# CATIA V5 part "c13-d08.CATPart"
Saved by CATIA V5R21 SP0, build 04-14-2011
Part number: Part1
Material "Alpine Fir": density 500 kg/m3, Young's modulus 1.7e+10 Pa, Poisson ratio 0.45, thermal expansion 3.75e-06 1/K
Bounding box of the stored display mesh (mm): x -163 to 95, y -77.362 to 77.362, z -85 to 85
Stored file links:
  D:\CATIA V5R21 E-RESOURCES\CATIA-V5R21\catia-v5r21-Prts\c13_catia_v5r21_prt\c13_catia_v5r21_figr_13-29 & 30\c13-d08.CATPart
  C:\Program Files\Dassault Systemes\B21\win_b64\startup\materials\Catalog.CATMaterial
  C:\Program Files\Dassault Systemes\B21\win_b64\startup\materials\alpin_fir.jpg
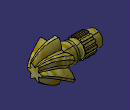
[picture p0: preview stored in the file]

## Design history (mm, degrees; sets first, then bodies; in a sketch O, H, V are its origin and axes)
Set1
  Plane1: type Offset, RefPlane face of Shaft1, Offset 45, reversed
  Plane2: type Offset, RefPlane Plane1, Offset 50, reversed
Body1 (main body), material "Alpine Fir"
  Sketch1 on zx-plane, origin (0, 0, 0), H (-1, 0, 0), V (0, 0, 1)
    axis line L1 (0, 0) -> (170, 0)
    line L2 (0, 0) -> (0, -45)
    point P2 (0, -45)
    line L3 (0, -45) -> (5, -45)
    point P3 (5, -45)
    line L4 (5, -45) -> (5, -39)
    line L5 (5, -39) -> (51, -39)
    line L6 (51, -39) -> (51, -38)
    point P6 (51, -38)
    line L7 (51, -38) -> (61, -38)
    point P7 (61, -38)
    line L8 (61, -38) -> (61, -36)
    point P8 (61, -36)
    arc A1 centre (72, -36) radius 11 from (61, -36) to (83, -36) cw
    point P10 (83, -36)
    line L9 (83, -36) -> (131, -36)
    line L10 (131, -36) -> (131, -32.5)
    line L11 (131, -32.5) -> (163, -32.5)
    line L12 (163, -32.5) -> (163, 0)
    point P14 (163, 0)
    line L13 (163, 0) -> (0, 0)
    "Radius" L11 L1 = 32.5
    "Radius" L9 L1 = 36
    "Radius" P7 L1 = 38
    "Radius" L5 L1 = 39
    "Radius" P3 L1 = 45
    length L11 = 32
    length L9 = 48
    distance P10 P8 = 22
    distance P7 P6 = 10
    length L5 = 46
    distance P3 P2 = 5
    horizontal: L1 H, L3 H, L5 H, L7 H, L9 H, L11 H, L13 H
    vertical: L2 V, L4 V, L6 V, L8 V, L12 V, L10 V
    tangency: A1 L8
    coincidence: P14 L1
  Shaft1: profile Sketch1, axis Sketch1.L1, angle 360
  Sketch2 on face of Shaft1, origin (-131, 0, 0), H (0, -1, 0), V (0, 0, 1)
    projected circle E1 centre (0, 0) radius 36 from edge [face of Shaft1 | face of Shaft1]
    projected arc E2 centre (0, 0) radius 36 from (5, 35.6511) to (-5, 35.6511) ccw from edge [face of Shaft1 | face of Shaft1]
    axis line L1 (0, 0) -> (0, 17.1744)
    point P2 (-5, 35.6511)
    line L2 (-5, 35.6511) -> (-5, 40.6511)
    point P3 (-5, 40.6511)
    line L3 (-5, 40.6511) -> (0, 40.6511)
    point P4 (0, 40.6511)
    point P5 (0, 40.6511)
    point P6 (5, 40.6511)
    line L4 (5, 40.6511) -> (0, 40.6511)
    point P7 (5, 35.6511)
    line L5 (5, 35.6511) -> (5, 40.6511)
    length L5 = 5
    distance L5 L2 = 10
    vertical: L1 V, L2 V
    coincidence: P2 E1, P4 L1, P4 P5
    horizontal: L3 H
    symmetry: P4 P5 L1, P3 P6 L1, L3 L4 L1, P2 P7 L1, L2 L5 L1
  Pad1: profile Sketch2, direction (1, 0, 0), length 48
  CircPattern1: of Pad1, instances 13, angular step 27.6923 {= 360.0*1 deg/CircPattern1.AngularNumber}, axis from face of Shaft1
  Loft1: solid, Sections (Sketch5; Sketch4; Sketch3)
  Sketch3 on Plane2, origin (95, 0, 0), H (0, -1, 0), V (0, 0, 1)
    construction line L1 through (0, 0) direction (1, 0)
    construction line L2 through (0, 0) direction (0, 1)
    arc A1 centre (23.3627, 6.7195) radius 24.375 from (13.5018, 29.0108) to (2.0971, 18.6324) ccw
    line L3 (18.3732, 26.1983) -> (13.5018, 29.0108)
    arc A2 centre (-5.8621, 23.5924) radius 24.375 from (15.0875, 11.1324) to (18.3732, 26.1983) ccw
    arc A3 centre (0, 0) radius 18.75 from (17.1847, 7.5) to (15.0875, 11.1324) ccw
    arc A4 centre (17.5006, -16.873) radius 24.375 from (31.875, 2.8125) to (17.1847, 7.5) ccw
    line L4 (31.875, -2.8125) -> (31.875, 2.8125)
    arc A5 centre (17.5006, 16.873) radius 24.375 from (17.1847, -7.5) to (31.875, -2.8125) ccw
    arc A6 centre (0, 0) radius 18.75 from (15.0875, -11.1324) to (17.1847, -7.5) ccw
    arc A7 centre (-5.8621, -23.5924) radius 24.375 from (18.3732, -26.1983) to (15.0875, -11.1324) ccw
    line L5 (13.5018, -29.0108) -> (18.3732, -26.1983)
    arc A8 centre (23.3627, -6.7195) radius 24.375 from (2.0971, -18.6324) to (13.5018, -29.0108) ccw
    arc A9 centre (0, 0) radius 18.75 from (-2.0971, -18.6324) to (2.0971, -18.6324) ccw
    arc A10 centre (-23.3627, -6.7195) radius 24.375 from (-13.5018, -29.0108) to (-2.0971, -18.6324) ccw
    line L6 (-18.3732, -26.1983) -> (-13.5018, -29.0108)
    arc A11 centre (5.8621, -23.5924) radius 24.375 from (-15.0875, -11.1324) to (-18.3732, -26.1983) ccw
    arc A12 centre (0, 0) radius 18.75 from (-17.1847, -7.5) to (-15.0875, -11.1324) ccw
    arc A13 centre (-17.5006, 16.873) radius 24.375 from (-31.875, -2.8125) to (-17.1847, -7.5) ccw
    line L7 (-31.875, 2.8125) -> (-31.875, -2.8125)
    arc A14 centre (-17.5006, -16.873) radius 24.375 from (-17.1847, 7.5) to (-31.875, 2.8125) ccw
    arc A15 centre (0, 0) radius 18.75 from (-15.0875, 11.1324) to (-17.1847, 7.5) ccw
    arc A16 centre (5.8621, 23.5924) radius 24.375 from (-18.3732, 26.1983) to (-15.0875, 11.1324) ccw
    line L8 (-13.5018, 29.0108) -> (-18.3732, 26.1983)
    arc A17 centre (-23.3627, 6.7195) radius 24.375 from (-2.0971, 18.6324) to (-13.5018, 29.0108) ccw
    arc A18 centre (0, 0) radius 18.75 from (2.0971, 18.6324) to (-2.0971, 18.6324) ccw
  Sketch4 on Plane1, origin (45, 0, 0), H (0, -1, 0), V (0, 0, 1)
    construction line L1 through (0, 0) direction (0.9659, -0.2588)
    construction line L2 through (0, 0) direction (0.2588, 0.9659)
    arc A1 centre (0, 0) radius 37.5 from (5.5935, -37.0805) to (13.6962, -34.9094) ccw
    arc A2 centre (-41.655, -25.0745) radius 48.75 from (-11.0664, -63.0336) to (5.5935, -37.0805) ccw
    arc A3 centre (48.6115, -0.8876) radius 48.75 from (13.6962, -34.9094) to (41.1006, -49.0555) ccw
    line L3 (49.0555, -41.1006) -> (41.1006, -49.0555)
    arc A4 centre (0.8876, -48.6115) radius 48.75 from (49.0555, -41.1006) to (34.9094, -13.6962) ccw
    arc A5 centre (0, 0) radius 37.5 from (34.9094, -13.6962) to (37.0805, -5.5935) ccw
    arc A6 centre (25.0745, 41.655) radius 48.75 from (37.0805, -5.5935) to (63.0336, 11.0664) ccw
    line L4 (60.1219, 21.933) -> (63.0336, 11.0664)
    arc A7 centre (42.5426, -23.5371) radius 48.75 from (60.1219, 21.933) to (29.3159, 23.3843) ccw
    arc A8 centre (0, 0) radius 37.5 from (29.3159, 23.3843) to (23.3843, 29.3159) ccw
    arc A9 centre (-23.5371, 42.5426) radius 48.75 from (23.3843, 29.3159) to (21.933, 60.1219) ccw
    line L5 (11.0664, 63.0336) -> (21.933, 60.1219)
    arc A10 centre (41.655, 25.0745) radius 48.75 from (11.0664, 63.0336) to (-5.5935, 37.0805) ccw
    arc A11 centre (0, 0) radius 37.5 from (-5.5935, 37.0805) to (-13.6962, 34.9094) ccw
    arc A12 centre (-48.6115, 0.8876) radius 48.75 from (-13.6962, 34.9094) to (-41.1006, 49.0555) ccw
    line L6 (-49.0555, 41.1006) -> (-41.1006, 49.0555)
    arc A13 centre (-0.8876, 48.6115) radius 48.75 from (-49.0555, 41.1006) to (-34.9094, 13.6962) ccw
    arc A14 centre (0, 0) radius 37.5 from (-34.9094, 13.6962) to (-37.0805, 5.5935) ccw
    arc A15 centre (-25.0745, -41.655) radius 48.75 from (-37.0805, 5.5935) to (-63.0336, -11.0664) ccw
    line L7 (-60.1219, -21.933) -> (-63.0336, -11.0664)
    arc A16 centre (-42.5426, 23.5371) radius 48.75 from (-60.1219, -21.933) to (-29.3159, -23.3843) ccw
    arc A17 centre (0, 0) radius 37.5 from (-29.3159, -23.3843) to (-23.3843, -29.3159) ccw
    arc A18 centre (23.5371, -42.5426) radius 48.75 from (-23.3843, -29.3159) to (-21.933, -60.1219) ccw
    line L8 (-11.0664, -63.0336) -> (-21.933, -60.1219)
  Sketch5 on face of Shaft1, origin (0, 0, 0), H (0, 1, 0), V (0, 0, 1)
    arc A1 centre (44.9945, 46.6682) radius 65 from (-20, 45.8258) to (-7.5, 85) cw
    point P1 (-7.5, 85)
    point P2 (7.5, 85)
    arc A2 centre (-44.9945, 46.6682) radius 65 from (20, 45.8258) to (7.5, 85) ccw
    line L1 (-7.5, 85) -> (7.5, 85)
    point P3 (7.5, 85)
    point P4 (20, 45.8258)
    point P5 (-20, 45.8258)
    point P6 (0, 0)
    arc A3 centre (0, 0) radius 50 from (29.6863, 40.2334) to (20, 45.8258) ccw
    arc A4 centre (-17.9186, 62.3005) radius 65 from (-49.6863, 5.5924) to (-77.3622, 36.0048) cw
    arc A5 centre (-62.9132, -15.6323) radius 65 from (-29.6863, 40.2334) to (-69.8622, 48.9952) ccw
    line L2 (-77.3622, 36.0048) -> (-69.8622, 48.9952)
    arc A6 centre (-62.9132, 15.6323) radius 65 from (-29.6863, -40.2334) to (-69.8622, -48.9952) cw
    arc A7 centre (-17.9186, -62.3005) radius 65 from (-49.6863, -5.5924) to (-77.3622, -36.0048) ccw
    line L3 (-69.8622, -48.9952) -> (-77.3622, -36.0048)
    arc A8 centre (-44.9945, -46.6682) radius 65 from (20, -45.8258) to (7.5, -85) cw
    arc A9 centre (44.9945, -46.6682) radius 65 from (-20, -45.8258) to (-7.5, -85) ccw
    line L4 (7.5, -85) -> (-7.5, -85)
    arc A10 centre (17.9186, -62.3005) radius 65 from (49.6863, -5.5924) to (77.3622, -36.0048) cw
    arc A11 centre (62.9132, 15.6323) radius 65 from (29.6863, -40.2334) to (69.8622, -48.9952) ccw
    line L5 (77.3622, -36.0048) -> (69.8622, -48.9952)
    arc A12 centre (62.9132, -15.6323) radius 65 from (29.6863, 40.2334) to (69.8622, 48.9952) cw
    arc A13 centre (17.9186, 62.3005) radius 65 from (49.6863, 5.5924) to (77.3622, 36.0048) ccw
    line L6 (69.8622, 48.9952) -> (77.3622, 36.0048)
    arc A14 centre (0, 0) radius 50 from (-49.6863, 5.5924) to (-49.6863, -5.5924) ccw
    arc A15 centre (0, 0) radius 50 from (-29.6863, -40.2334) to (-20, -45.8258) ccw
    arc A16 centre (0, 0) radius 50 from (20, -45.8258) to (29.6863, -40.2334) ccw
    arc A17 centre (0, 0) radius 50 from (49.6863, -5.5924) to (49.6863, 5.5924) ccw
    arc A18 centre (0, 0) radius 50 from (-20, 45.8258) to (-29.6863, 40.2334) ccw
    distance P4 P5 = 40
    radius A2 = 65
    length L1 = 15
    distance P6 L1 = 85
    radius A3 = 50
    symmetry: P1 P2 V, A1 A2 V, P4 P5 V
    coincidence: P3 A2, P6 O, P5 A3, A3 A14, A14 A15, A15 A16, A16 A17, A3 A18
    horizontal: L1 H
